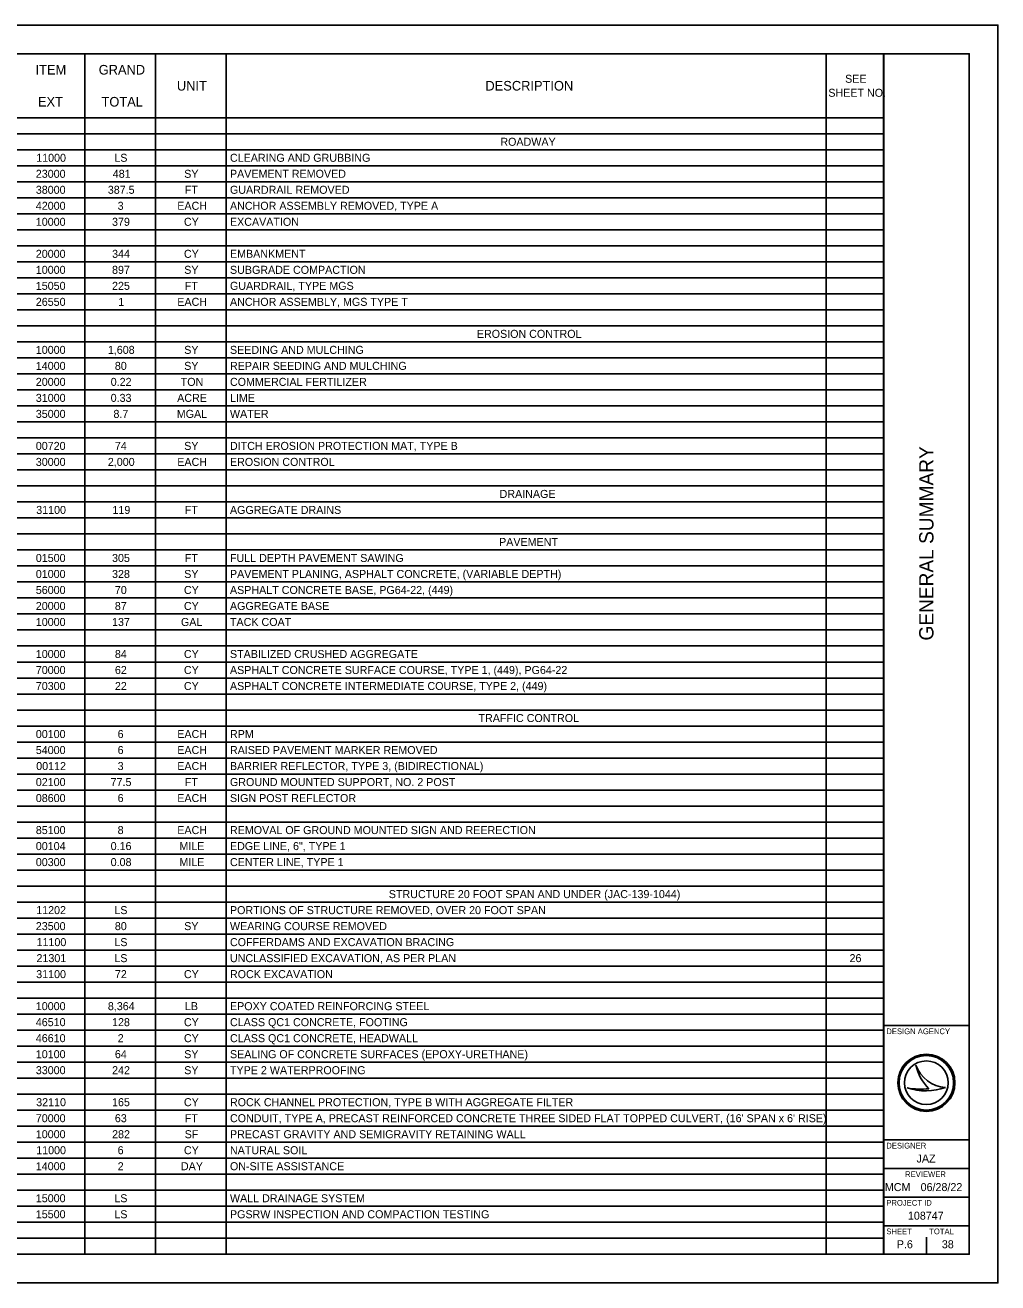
# Model space of a CAD drawing. Extents: x 0 to 34, y 0 to 22.
# Drawn here: x 16.99 to 34, y 0 to 22 of the extents above; entities that cross this region are included whole.
import ezdxf

# ---------------------------------------------------------------- set-up
doc = ezdxf.new("R2010")
doc.units = 0
for name, color, linetype in [('SH_Border', 7, 'Continuous'), ('SH_Cut_Line', 7, 'Continuous'), ('SH_Data', 7, 'Continuous'), ('SH_Text', 7, 'Continuous')]:
    doc.layers.add(name, color=color, linetype=linetype)

msp = doc.modelspace()

# ---------------------------------------------------------------- linework, layer by layer
at = {"layer": 'SH_Border'}
for p, q in [((32, 0.5), (32, 21.5)), ((32, 4.5), (33.5, 4.5)), ((32, 2.5), (33.5, 2.5)), ((32, 2), (33.5, 2)), ((32, 1.5), (33.5, 1.5)), ((32, 1), (33.5, 1))]:
    msp.add_line(p, q, dxfattribs=at)
msp.add_lwpolyline([(1.5, 21.5), (33.5, 21.5), (33.5, 0.5), (1.5, 0.5)], close=True, dxfattribs=at)
at = {"layer": 'SH_Cut_Line'}
msp.add_lwpolyline([(0, 0), (34, 0), (34, 22), (0, 22)], close=True, dxfattribs=at)
at = {"layer": 'SH_Data'}
for p, q in [((32.567, 3.81), (32.567, 3.81)), ((32.417, 3.41), (32.417, 3.41)), ((32.75, 3.5), (32.75, 3.5)), ((33.087, 3.419), (33.087, 3.419)), ((32.375, 0.675), (32.375, 0.675)), ((32.75, 0.5), (32.75, 0.8))]:
    msp.add_line(p, q, dxfattribs=at)
for radius in [0.5, 0.477, 0.477, 0.382]:
    msp.add_circle((32.75, 3.5), radius, dxfattribs=at)
for centre, radius, start, end in [((33.116, 3.998), 0.58, 198.9257, 198.9319), ((33.347, 3.97), 0.796, 191.6379, 191.6421), ((33.116, 3.998), 0.58, 198.9319, 267.1657), ((33.347, 3.97), 0.796, 191.6421, 226.0947), ((32.739, 4.37), 1.013, 251.4576, 290.0832), ((32.648, 4.654), 1.266, 259.4964, 259.4995), ((32.739, 4.37), 1.013, 251.4527, 251.4576), ((32.648, 4.654), 1.266, 259.4995, 276.6672)]:
    msp.add_arc(centre, radius, start, end, dxfattribs=at)
at = {"layer": 'SH_Text'}
for p, q in [((1.5, 21.5), (32.004, 21.5)), ((18.036, 21.5), (18.036, 0.5)), ((19.272, 21.5), (19.272, 0.5)), ((20.507, 21.5), (20.507, 0.5)), ((30.999, 21.5), (30.999, 0.5)), ((32.004, 21.5), (32.004, 0.5)), ((1.5, 20.38), (32.004, 20.38)), ((1.5, 20.1), (32.004, 20.1)), ((1.5, 19.82), (32.004, 19.82)), ((1.5, 19.54), (32.004, 19.54)), ((1.5, 19.26), (32.004, 19.26)), ((1.5, 18.98), (32.004, 18.98)), ((1.5, 18.7), (32.004, 18.7)), ((1.5, 18.42), (32.004, 18.42)), ((1.5, 18.14), (32.004, 18.14)), ((1.5, 17.86), (32.004, 17.86)), ((1.5, 17.58), (32.004, 17.58)), ((1.5, 17.3), (32.004, 17.3)), ((1.5, 17.02), (32.004, 17.02)), ((1.5, 16.74), (32.004, 16.74)), ((1.5, 16.46), (32.004, 16.46)), ((1.5, 16.18), (32.004, 16.18)), ((1.5, 15.9), (32.004, 15.9)), ((1.5, 15.62), (32.004, 15.62)), ((1.5, 15.34), (32.004, 15.34)), ((1.5, 15.06), (32.004, 15.06)), ((1.5, 14.78), (32.004, 14.78)), ((1.5, 14.5), (32.004, 14.5)), ((1.5, 14.22), (32.004, 14.22)), ((1.5, 13.94), (32.004, 13.94)), ((1.5, 13.66), (32.004, 13.66)), ((1.5, 13.38), (32.004, 13.38)), ((1.5, 13.1), (32.004, 13.1)), ((1.5, 12.82), (32.004, 12.82)), ((1.5, 12.54), (32.004, 12.54)), ((1.5, 12.26), (32.004, 12.26)), ((1.5, 11.98), (32.004, 11.98)), ((1.5, 11.7), (32.004, 11.7)), ((1.5, 11.42), (32.004, 11.42)), ((1.5, 11.14), (32.004, 11.14)), ((1.5, 10.86), (32.004, 10.86)), ((1.5, 10.58), (32.004, 10.58)), ((1.5, 10.3), (32.004, 10.3)), ((1.5, 10.02), (32.004, 10.02)), ((1.5, 9.74), (32.004, 9.74)), ((1.5, 9.46), (32.004, 9.46)), ((1.5, 9.18), (32.004, 9.18)), ((1.5, 8.9), (32.004, 8.9)), ((1.5, 8.62), (32.004, 8.62)), ((1.5, 8.34), (32.004, 8.34)), ((1.5, 8.06), (32.004, 8.06)), ((1.5, 7.78), (32.004, 7.78)), ((1.5, 7.5), (32.004, 7.5)), ((1.5, 7.22), (32.004, 7.22)), ((1.5, 6.94), (32.004, 6.94)), ((1.5, 6.66), (32.004, 6.66)), ((1.5, 6.38), (32.004, 6.38)), ((1.5, 6.1), (32.004, 6.1)), ((1.5, 5.82), (32.004, 5.82)), ((1.5, 5.54), (32.004, 5.54)), ((1.5, 5.26), (32.004, 5.26)), ((1.5, 4.98), (32.004, 4.98)), ((1.5, 4.7), (32.004, 4.7)), ((1.5, 4.42), (32.004, 4.42)), ((1.5, 4.14), (32.004, 4.14)), ((1.5, 3.86), (32.004, 3.86)), ((1.5, 3.58), (32.004, 3.58)), ((1.5, 3.3), (32.004, 3.3)), ((1.5, 3.02), (32.004, 3.02)), ((1.5, 2.74), (32.004, 2.74)), ((1.5, 2.46), (32.004, 2.46)), ((1.5, 2.18), (32.004, 2.18)), ((1.5, 1.9), (32.004, 1.9)), ((1.5, 1.62), (32.004, 1.62)), ((1.5, 1.34), (32.004, 1.34)), ((1.5, 1.06), (32.004, 1.06)), ((1.5, 0.78), (32.004, 0.78)), ((1.5, 0.5), (32.004, 0.5))]:
    msp.add_line(p, q, dxfattribs=at)

# ---------------------------------------------------------------- texts
at = {"layer": 'SH_Data'}
msp.add_text('GENERAL SUMMARY', height=0.25, rotation=90, dxfattribs=at).set_placement((32.875, 11.235))
for s, height, p in [('DESIGN AGENCY', 0.1, (32.05, 4.35)), ('DESIGNER', 0.1, (32.05, 2.35)), ('JAZ', 0.14, (32.579, 2.105)), ('REVIEWER', 0.1, (32.378, 1.85)), ('MCM', 0.14, (32.024, 1.605)), ('06/28/22', 0.14, (32.65, 1.605)), ('PROJECT ID', 0.1, (32.05, 1.35)), ('108747', 0.14, (32.428, 1.105)), ('SHEET', 0.1, (32.05, 0.85)), ('TOTAL', 0.1, (32.8, 0.85)), ('P.6', 0.14, (32.233, 0.605)), ('38', 0.14, (33.021, 0.605))]:
    msp.add_text(s, height=height, dxfattribs=at).set_placement(p)
at = {"layer": 'SH_Text'}
for s, height, p in [('ITEM', 0.168, (17.174, 21.136)), ('GRAND', 0.168, (18.278, 21.136)), ('SEE ', 0.14, (31.33, 20.992)), ('UNIT', 0.168, (19.645, 20.856)), ('DESCRIPTION', 0.168, (25.04, 20.856)), ('EXT', 0.168, (17.215, 20.576)), ('TOTAL', 0.168, (18.327, 20.576)), ('SHEET NO.', 0.14, (31.036, 20.747)), ('ROADWAY', 0.14, (25.301, 19.89)), ('11000', 0.14, (17.185, 19.61)), ('LS', 0.14, (18.551, 19.61)), ('CLEARING AND GRUBBING', 0.14, (20.573, 19.61)), ('23000', 0.14, (17.178, 19.33)), ('481', 0.14, (18.524, 19.33)), ('SY', 0.14, (19.773, 19.33)), ('PAVEMENT REMOVED', 0.14, (20.573, 19.33)), ('38000', 0.14, (17.178, 19.05)), ('387.5', 0.14, (18.437, 19.05)), ('FT', 0.14, (19.784, 19.05)), ('GUARDRAIL REMOVED', 0.14, (20.573, 19.05)), ('42000', 0.14, (17.178, 18.77)), ('3', 0.14, (18.609, 18.77)), ('EACH', 0.14, (19.652, 18.77)), ('ANCHOR ASSEMBLY REMOVED, TYPE A', 0.14, (20.573, 18.77)), ('10000', 0.14, (17.178, 18.49)), ('379', 0.14, (18.511, 18.49)), ('CY', 0.14, (19.768, 18.49)), ('EXCAVATION', 0.14, (20.573, 18.49)), ('20000', 0.14, (17.178, 17.93)), ('344', 0.14, (18.512, 17.93)), ('CY', 0.14, (19.768, 17.93)), ('EMBANKMENT', 0.14, (20.573, 17.93)), ('10000', 0.14, (17.178, 17.65)), ('897', 0.14, (18.511, 17.65)), ('SY', 0.14, (19.773, 17.65)), ('SUBGRADE COMPACTION', 0.14, (20.573, 17.65)), ('15050', 0.14, (17.178, 17.37)), ('225', 0.14, (18.511, 17.37)), ('FT', 0.14, (19.784, 17.37)), ('GUARDRAIL, TYPE MGS', 0.14, (20.573, 17.37)), ('26550', 0.14, (17.178, 17.09)), ('1', 0.14, (18.621, 17.09)), ('EACH', 0.14, (19.652, 17.09)), ('ANCHOR ASSEMBLY, MGS TYPE T', 0.14, (20.573, 17.09)), ('EROSION CONTROL', 0.14, (24.89, 16.53)), ('10000', 0.14, (17.178, 16.25)), ('1,608', 0.14, (18.438, 16.25)), ('SY', 0.14, (19.773, 16.25)), ('SEEDING AND MULCHING', 0.14, (20.573, 16.25)), ('14000', 0.14, (17.178, 15.97)), ('80', 0.14, (18.56, 15.97)), ('SY', 0.14, (19.773, 15.97)), ('REPAIR SEEDING AND MULCHING', 0.14, (20.573, 15.97)), ('20000', 0.14, (17.178, 15.69)), ('0.22', 0.14, (18.488, 15.69)), ('TON', 0.14, (19.712, 15.69)), ('COMMERCIAL FERTILIZER', 0.14, (20.573, 15.69)), ('31000', 0.14, (17.178, 15.41)), ('0.33', 0.14, (18.487, 15.41)), ('ACRE', 0.14, (19.65, 15.41)), ('LIME', 0.14, (20.573, 15.41)), ('35000', 0.14, (17.178, 15.13)), ('8.7', 0.14, (18.536, 15.13)), ('MGAL', 0.14, (19.643, 15.13)), ('WATER', 0.14, (20.573, 15.13)), ('00720', 0.14, (17.178, 14.57)), ('74', 0.14, (18.561, 14.57)), ('SY', 0.14, (19.773, 14.57)), ('DITCH EROSION PROTECTION MAT, TYPE B', 0.14, (20.573, 14.57)), ('30000', 0.14, (17.178, 14.29)), ('2,000', 0.14, (18.438, 14.29)), ('EACH', 0.14, (19.652, 14.29)), ('EROSION CONTROL', 0.14, (20.573, 14.29)), ('DRAINAGE', 0.14, (25.288, 13.73)), ('31100', 0.14, (17.185, 13.45)), ('119', 0.14, (18.518, 13.45)), ('FT', 0.14, (19.784, 13.45)), ('AGGREGATE DRAINS', 0.14, (20.573, 13.45)), ('PAVEMENT', 0.14, (25.279, 12.89)), ('01500', 0.14, (17.178, 12.61)), ('305', 0.14, (18.511, 12.61)), ('FT', 0.14, (19.784, 12.61)), ('FULL DEPTH PAVEMENT SAWING', 0.14, (20.573, 12.61)), ('01000', 0.14, (17.178, 12.33)), ('328', 0.14, (18.511, 12.33)), ('SY', 0.14, (19.773, 12.33)), ('PAVEMENT PLANING, ASPHALT CONCRETE, (VARIABLE DEPTH)', 0.14, (20.573, 12.33)), ('56000', 0.14, (17.178, 12.05)), ('70', 0.14, (18.56, 12.05)), ('CY', 0.14, (19.768, 12.05)), ('ASPHALT CONCRETE BASE, PG64-22, (449)', 0.14, (20.573, 12.05)), ('20000', 0.14, (17.178, 11.77)), ('87', 0.14, (18.56, 11.77)), ('CY', 0.14, (19.768, 11.77)), ('AGGREGATE BASE', 0.14, (20.573, 11.77)), ('10000', 0.14, (17.178, 11.49)), ('137', 0.14, (18.511, 11.49)), ('GAL', 0.14, (19.716, 11.49)), ('TACK COAT', 0.14, (20.573, 11.49)), ('10000', 0.14, (17.178, 10.93)), ('84', 0.14, (18.561, 10.93)), ('CY', 0.14, (19.768, 10.93)), ('STABILIZED CRUSHED AGGREGATE', 0.14, (20.573, 10.93)), ('70000', 0.14, (17.178, 10.65)), ('62', 0.14, (18.561, 10.65)), ('CY', 0.14, (19.768, 10.65)), ('ASPHALT CONCRETE SURFACE COURSE, TYPE 1, (449), PG64-22', 0.14, (20.573, 10.65)), ('70300', 0.14, (17.178, 10.37)), ('22', 0.14, (18.561, 10.37)), ('CY', 0.14, (19.768, 10.37)), ('ASPHALT CONCRETE INTERMEDIATE COURSE, TYPE 2, (449)', 0.14, (20.573, 10.37)), ('TRAFFIC CONTROL', 0.14, (24.919, 9.81)), ('00100', 0.14, (17.178, 9.53)), ('6', 0.14, (18.609, 9.53)), ('EACH', 0.14, (19.652, 9.53)), ('RPM', 0.14, (20.573, 9.53)), ('54000', 0.14, (17.178, 9.25)), ('6', 0.14, (18.609, 9.25)), ('EACH', 0.14, (19.652, 9.25)), ('RAISED PAVEMENT MARKER REMOVED', 0.14, (20.573, 9.25)), ('00112', 0.14, (17.185, 8.97)), ('3', 0.14, (18.609, 8.97)), ('EACH', 0.14, (19.652, 8.97)), ('BARRIER REFLECTOR, TYPE 3, (BIDIRECTIONAL)', 0.14, (20.573, 8.97)), ('02100', 0.14, (17.178, 8.69)), ('77.5', 0.14, (18.486, 8.69)), ('FT', 0.14, (19.784, 8.69)), ('GROUND MOUNTED SUPPORT, NO. 2 POST', 0.14, (20.573, 8.69)), ('08600', 0.14, (17.178, 8.41)), ('6', 0.14, (18.609, 8.41)), ('EACH', 0.14, (19.652, 8.41)), ('SIGN POST REFLECTOR', 0.14, (20.573, 8.41)), ('85100', 0.14, (17.178, 7.85)), ('8', 0.14, (18.609, 7.85)), ('EACH', 0.14, (19.652, 7.85)), ('REMOVAL OF GROUND MOUNTED SIGN AND REERECTION', 0.14, (20.573, 7.85)), ('00104', 0.14, (17.178, 7.57)), ('0.16', 0.14, (18.487, 7.57)), ('MILE', 0.14, (19.689, 7.57)), ('EDGE LINE, 6", TYPE 1', 0.14, (20.573, 7.57)), ('00300', 0.14, (17.178, 7.29)), ('0.08', 0.14, (18.487, 7.29)), ('MILE', 0.14, (19.689, 7.29)), ('CENTER LINE, TYPE 1', 0.14, (20.573, 7.29)), ('STRUCTURE 20 FOOT SPAN AND UNDER (JAC-139-1044)', 0.14, (23.351, 6.73)), ('11202', 0.14, (17.185, 6.45)), ('LS', 0.14, (18.551, 6.45)), ('PORTIONS OF STRUCTURE REMOVED, OVER 20 FOOT SPAN', 0.14, (20.573, 6.45)), ('23500', 0.14, (17.178, 6.17)), ('80', 0.14, (18.56, 6.17)), ('SY', 0.14, (19.773, 6.17)), ('WEARING COURSE REMOVED', 0.14, (20.573, 6.17)), ('11100', 0.14, (17.191, 5.89)), ('LS', 0.14, (18.551, 5.89)), ('COFFERDAMS AND EXCAVATION BRACING', 0.14, (20.573, 5.89)), ('21301', 0.14, (17.19, 5.61)), ('LS', 0.14, (18.551, 5.61)), ('UNCLASSIFIED EXCAVATION, AS PER PLAN', 0.14, (20.573, 5.61)), ('26', 0.14, (31.407, 5.61)), ('31100', 0.14, (17.185, 5.33)), ('72', 0.14, (18.561, 5.33)), ('CY', 0.14, (19.768, 5.33)), ('ROCK EXCAVATION', 0.14, (20.573, 5.33)), ('10000', 0.14, (17.178, 4.77)), ('8,364', 0.14, (18.438, 4.77)), ('LB', 0.14, (19.786, 4.77)), ('EPOXY COATED REINFORCING STEEL', 0.14, (20.573, 4.77)), ('46510', 0.14, (17.178, 4.49)), ('128', 0.14, (18.511, 4.49)), ('CY', 0.14, (19.768, 4.49)), ('CLASS QC1 CONCRETE, FOOTING', 0.14, (20.573, 4.49)), ('46610', 0.14, (17.178, 4.21)), ('2', 0.14, (18.61, 4.21)), ('CY', 0.14, (19.768, 4.21)), ('CLASS QC1 CONCRETE, HEADWALL', 0.14, (20.573, 4.21)), ('10100', 0.14, (17.178, 3.93)), ('64', 0.14, (18.561, 3.93)), ('SY', 0.14, (19.773, 3.93)), ('SEALING OF CONCRETE SURFACES (EPOXY-URETHANE)', 0.14, (20.573, 3.93)), ('33000', 0.14, (17.178, 3.65)), ('242', 0.14, (18.512, 3.65)), ('SY', 0.14, (19.773, 3.65)), ('TYPE 2 WATERPROOFING', 0.14, (20.573, 3.65)), ('32110', 0.14, (17.185, 3.09)), ('165', 0.14, (18.511, 3.09)), ('CY', 0.14, (19.768, 3.09)), ('ROCK CHANNEL PROTECTION, TYPE B WITH AGGREGATE FILTER', 0.14, (20.573, 3.09)), ('70000', 0.14, (17.178, 2.81)), ('63', 0.14, (18.56, 2.81)), ('FT', 0.14, (19.784, 2.81)), ("CONDUIT, TYPE A, PRECAST REINFORCED CONCRETE THREE SIDED FLAT TOPPED CULVERT, (16' SPAN x 6' RISE)", 0.14, (20.573, 2.81)), ('10000', 0.14, (17.178, 2.53)), ('282', 0.14, (18.512, 2.53)), ('SF', 0.14, (19.781, 2.53)), ('PRECAST GRAVITY AND SEMIGRAVITY RETAINING WALL', 0.14, (20.573, 2.53)), ('11000', 0.14, (17.185, 2.25)), ('6', 0.14, (18.609, 2.25)), ('CY', 0.14, (19.768, 2.25)), ('NATURAL SOIL', 0.14, (20.573, 2.25)), ('14000', 0.14, (17.178, 1.97)), ('2', 0.14, (18.61, 1.97)), ('DAY', 0.14, (19.716, 1.97)), ('ON-SITE ASSISTANCE', 0.14, (20.573, 1.97)), ('15000', 0.14, (17.178, 1.41)), ('LS', 0.14, (18.551, 1.41)), ('WALL DRAINAGE SYSTEM', 0.14, (20.573, 1.41)), ('15500', 0.14, (17.178, 1.13)), ('LS', 0.14, (18.551, 1.13)), ('PGSRW INSPECTION AND COMPACTION TESTING', 0.14, (20.573, 1.13))]:
    msp.add_text(s, height=height, dxfattribs=at).set_placement(p)

doc.saveas('drawing.dxf')
